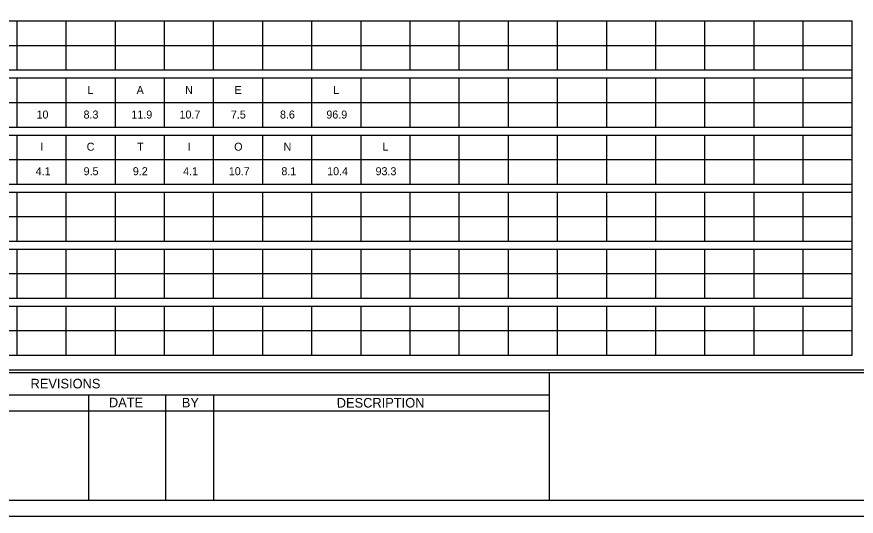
# Model space of a CAD drawing. Extents: x 17890628 to 17890844, y 17897506 to 17897992.
# Drawn here: x 17890726.43 to 17890772.14, y 17897507.81 to 17897535.03 of the extents above; entities that cross this region are included whole.
import ezdxf

# ---------------------------------------------------------------- set-up
doc = ezdxf.new("R2010")
doc.units = 0
for name, color, linetype in [('GSSign', 7, 'Continuous'), ('PlotBorder_dp', 7, 'Continuous'), ('SheetBorder_dp', 7, 'Continuous'), ('SheetLines_dp', 7, 'Continuous'), ('SheetLinesMisc2_dp', 7, 'Continuous'), ('TextMisc', 7, 'Continuous')]:
    doc.layers.add(name, color=color, linetype=linetype)

msp = doc.modelspace()

# ---------------------------------------------------------------- linework, layer by layer
at = {"layer": 'PlotBorder_dp'}
msp.add_lwpolyline([(17890700.471, 17897507.81), (17890844.155, 17897507.81), (17890844.155, 17897600.116), (17890700.471, 17897600.116)], close=True, dxfattribs=at)
at = {"layer": 'SheetBorder_dp'}
for p, q in [((17890705.26, 17897515.647), (17890839.365, 17897515.647)), ((17890705.26, 17897508.681), (17890839.365, 17897508.681))]:
    msp.add_line(p, q, dxfattribs=at)
at = {"layer": 'SheetLines_dp'}
for p, q in [((17890755.419, 17897515.647), (17890755.419, 17897508.681)), ((17890705.26, 17897514.428), (17890755.419, 17897514.428)), ((17890730.339, 17897514.428), (17890730.339, 17897508.681)), ((17890734.519, 17897514.428), (17890734.519, 17897508.681)), ((17890737.132, 17897514.428), (17890737.132, 17897508.681)), ((17890705.26, 17897513.557), (17890755.419, 17897513.557))]:
    msp.add_line(p, q, dxfattribs=at)
at = {"layer": 'SheetLinesMisc2_dp'}
for p, q in [((17890706.142, 17897534.804), (17890771.912, 17897534.804)), ((17890726.429, 17897534.804), (17890726.429, 17897532.131)), ((17890729.104, 17897534.804), (17890729.104, 17897532.131)), ((17890731.779, 17897534.804), (17890731.779, 17897532.131)), ((17890734.455, 17897534.804), (17890734.455, 17897532.131)), ((17890737.131, 17897534.804), (17890737.131, 17897532.131)), ((17890739.806, 17897534.804), (17890739.806, 17897532.131)), ((17890742.481, 17897534.804), (17890742.481, 17897532.131)), ((17890745.157, 17897534.804), (17890745.157, 17897532.131)), ((17890747.833, 17897534.804), (17890747.833, 17897532.131)), ((17890750.508, 17897534.804), (17890750.508, 17897532.131)), ((17890753.183, 17897534.804), (17890753.183, 17897532.131)), ((17890755.859, 17897534.804), (17890755.859, 17897532.131)), ((17890758.535, 17897534.804), (17890758.535, 17897532.131)), ((17890761.21, 17897534.804), (17890761.21, 17897532.131)), ((17890763.885, 17897534.804), (17890763.885, 17897532.131)), ((17890766.561, 17897534.804), (17890766.561, 17897532.131)), ((17890769.237, 17897534.804), (17890769.237, 17897532.131)), ((17890771.912, 17897516.593), (17890771.912, 17897534.804)), ((17890706.142, 17897533.468), (17890771.912, 17897533.468)), ((17890706.142, 17897532.131), (17890771.912, 17897532.131)), ((17890706.142, 17897531.696), (17890771.912, 17897531.696)), ((17890726.429, 17897531.696), (17890726.429, 17897529.023)), ((17890729.104, 17897531.696), (17890729.104, 17897529.023)), ((17890731.779, 17897531.696), (17890731.779, 17897529.023)), ((17890734.455, 17897531.696), (17890734.455, 17897529.023)), ((17890737.131, 17897531.696), (17890737.131, 17897529.023)), ((17890739.806, 17897531.696), (17890739.806, 17897529.023)), ((17890742.481, 17897531.696), (17890742.481, 17897529.023)), ((17890745.157, 17897531.696), (17890745.157, 17897529.023)), ((17890747.833, 17897531.696), (17890747.833, 17897529.023)), ((17890750.508, 17897531.696), (17890750.508, 17897529.023)), ((17890753.183, 17897531.696), (17890753.183, 17897529.023)), ((17890755.859, 17897531.696), (17890755.859, 17897529.023)), ((17890758.535, 17897531.696), (17890758.535, 17897529.023)), ((17890761.21, 17897531.696), (17890761.21, 17897529.023)), ((17890763.885, 17897531.696), (17890763.885, 17897529.023)), ((17890766.561, 17897531.696), (17890766.561, 17897529.023)), ((17890769.237, 17897531.696), (17890769.237, 17897529.023)), ((17890706.142, 17897530.359), (17890771.912, 17897530.359)), ((17890706.142, 17897529.023), (17890771.912, 17897529.023)), ((17890706.142, 17897528.588), (17890771.912, 17897528.588)), ((17890726.429, 17897528.588), (17890726.429, 17897525.916)), ((17890729.104, 17897528.588), (17890729.104, 17897525.916)), ((17890731.779, 17897528.588), (17890731.779, 17897525.916)), ((17890734.455, 17897528.588), (17890734.455, 17897525.916)), ((17890737.131, 17897528.588), (17890737.131, 17897525.916)), ((17890739.806, 17897528.588), (17890739.806, 17897525.916)), ((17890742.481, 17897528.588), (17890742.481, 17897525.916)), ((17890745.157, 17897528.588), (17890745.157, 17897525.916)), ((17890747.833, 17897528.588), (17890747.833, 17897525.916)), ((17890750.508, 17897528.588), (17890750.508, 17897525.916)), ((17890753.183, 17897528.588), (17890753.183, 17897525.916)), ((17890755.859, 17897528.588), (17890755.859, 17897525.916)), ((17890758.535, 17897528.588), (17890758.535, 17897525.916)), ((17890761.21, 17897528.588), (17890761.21, 17897525.916)), ((17890763.885, 17897528.588), (17890763.885, 17897525.916)), ((17890766.561, 17897528.588), (17890766.561, 17897525.916)), ((17890769.237, 17897528.588), (17890769.237, 17897525.916)), ((17890706.142, 17897527.252), (17890771.912, 17897527.252)), ((17890706.142, 17897525.916), (17890771.912, 17897525.916)), ((17890706.142, 17897525.48), (17890771.912, 17897525.48)), ((17890726.429, 17897525.48), (17890726.429, 17897522.808)), ((17890729.104, 17897525.48), (17890729.104, 17897522.808)), ((17890731.779, 17897525.48), (17890731.779, 17897522.808)), ((17890734.455, 17897525.48), (17890734.455, 17897522.808)), ((17890737.131, 17897525.48), (17890737.131, 17897522.808)), ((17890739.806, 17897525.48), (17890739.806, 17897522.808)), ((17890742.481, 17897525.48), (17890742.481, 17897522.808)), ((17890745.157, 17897525.48), (17890745.157, 17897522.808)), ((17890747.833, 17897525.48), (17890747.833, 17897522.808)), ((17890750.508, 17897525.48), (17890750.508, 17897522.808)), ((17890753.183, 17897525.48), (17890753.183, 17897522.808)), ((17890755.859, 17897525.48), (17890755.859, 17897522.808)), ((17890758.535, 17897525.48), (17890758.535, 17897522.808)), ((17890761.21, 17897525.48), (17890761.21, 17897522.808)), ((17890763.885, 17897525.48), (17890763.885, 17897522.808)), ((17890766.561, 17897525.48), (17890766.561, 17897522.808)), ((17890769.237, 17897525.48), (17890769.237, 17897522.808)), ((17890706.142, 17897524.145), (17890771.912, 17897524.145)), ((17890706.142, 17897522.808), (17890771.912, 17897522.808)), ((17890706.142, 17897522.372), (17890771.912, 17897522.372)), ((17890726.429, 17897522.372), (17890726.429, 17897519.7)), ((17890729.104, 17897522.372), (17890729.104, 17897519.7)), ((17890731.779, 17897522.372), (17890731.779, 17897519.7)), ((17890734.455, 17897522.372), (17890734.455, 17897519.7)), ((17890737.131, 17897522.372), (17890737.131, 17897519.7)), ((17890739.806, 17897522.372), (17890739.806, 17897519.7)), ((17890742.481, 17897522.372), (17890742.481, 17897519.7)), ((17890745.157, 17897522.372), (17890745.157, 17897519.7)), ((17890747.833, 17897522.372), (17890747.833, 17897519.7)), ((17890750.508, 17897522.372), (17890750.508, 17897519.7)), ((17890753.183, 17897522.372), (17890753.183, 17897519.7)), ((17890755.859, 17897522.372), (17890755.859, 17897519.7)), ((17890758.535, 17897522.372), (17890758.535, 17897519.7)), ((17890761.21, 17897522.372), (17890761.21, 17897519.7)), ((17890763.885, 17897522.372), (17890763.885, 17897519.7)), ((17890766.561, 17897522.372), (17890766.561, 17897519.7)), ((17890769.237, 17897522.372), (17890769.237, 17897519.7)), ((17890706.142, 17897521.036), (17890771.912, 17897521.036)), ((17890706.142, 17897519.7), (17890771.912, 17897519.7)), ((17890706.142, 17897519.264), (17890771.912, 17897519.264)), ((17890726.429, 17897519.264), (17890726.429, 17897516.593)), ((17890729.104, 17897519.264), (17890729.104, 17897516.593)), ((17890731.779, 17897519.264), (17890731.779, 17897516.593)), ((17890734.455, 17897519.264), (17890734.455, 17897516.593)), ((17890737.131, 17897519.264), (17890737.131, 17897516.593)), ((17890739.806, 17897519.264), (17890739.806, 17897516.593)), ((17890742.481, 17897519.264), (17890742.481, 17897516.593)), ((17890745.157, 17897519.264), (17890745.157, 17897516.593)), ((17890747.833, 17897519.264), (17890747.833, 17897516.593)), ((17890750.508, 17897519.264), (17890750.508, 17897516.593)), ((17890753.183, 17897519.264), (17890753.183, 17897516.593)), ((17890755.859, 17897519.264), (17890755.859, 17897516.593)), ((17890758.535, 17897519.264), (17890758.535, 17897516.593)), ((17890761.21, 17897519.264), (17890761.21, 17897516.593)), ((17890763.885, 17897519.264), (17890763.885, 17897516.593)), ((17890766.561, 17897519.264), (17890766.561, 17897516.593)), ((17890769.237, 17897519.264), (17890769.237, 17897516.593)), ((17890706.142, 17897517.928), (17890771.912, 17897517.928)), ((17890706.142, 17897516.593), (17890771.912, 17897516.593)), ((17890705.5, 17897515.791), (17890839.233, 17897515.791))]:
    msp.add_line(p, q, dxfattribs=at)

# ---------------------------------------------------------------- texts
at = {"layer": 'GSSign'}
for s, height, p in [('L', 0.436, (17890730.275, 17897530.822)), ('A', 0.436, (17890732.954, 17897530.822)), ('N', 0.436, (17890735.594, 17897530.822)), ('E', 0.436, (17890738.287, 17897530.822)), ('L', 0.436, (17890743.661, 17897530.822)), ('10', 0.4357, (17890727.504, 17897529.485)), ('8.3', 0.4357, (17890730.064, 17897529.485)), ('11.9', 0.4357, (17890732.67, 17897529.485)), ('10.7', 0.4357, (17890735.29, 17897529.485)), ('7.5', 0.4357, (17890738.088, 17897529.485)), ('8.6', 0.4357, (17890740.761, 17897529.485)), ('96.9', 0.4357, (17890743.287, 17897529.485)), ('I', 0.436, (17890727.715, 17897527.732)), ('C', 0.436, (17890730.234, 17897527.732)), ('T', 0.436, (17890732.981, 17897527.732)), ('I', 0.436, (17890735.741, 17897527.732)), ('O', 0.436, (17890738.268, 17897527.732)), ('N', 0.436, (17890740.958, 17897527.732)), ('L', 0.436, (17890746.34, 17897527.732)), ('4.1', 0.4357, (17890727.462, 17897526.396)), ('9.5', 0.4357, (17890730.066, 17897526.396)), ('9.2', 0.4357, (17890732.749, 17897526.396)), ('4.1', 0.4357, (17890735.488, 17897526.396)), ('10.7', 0.4357, (17890737.975, 17897526.396)), ('8.1', 0.4357, (17890740.838, 17897526.396)), ('10.4', 0.4357, (17890743.33, 17897526.396)), ('93.3', 0.4357, (17890745.967, 17897526.396))]:
    msp.add_text(s, height=height, dxfattribs=at).set_placement(p)
at = {"layer": 'TextMisc'}
for s, p in [('REVISIONS', (17890727.178, 17897514.776)), ('BY', (17890735.416, 17897513.74))]:
    msp.add_text(s, height=0.5225, dxfattribs=at).set_placement(p)
for s, height, rotation, p in [('DATE', 0.5225, 359.8693, (17890731.445, 17897513.749)), ('DESCRIPTION', 0.52238, 0.0498, (17890743.854, 17897513.731))]:
    msp.add_text(s, height=height, rotation=rotation, dxfattribs=at).set_placement(p)

doc.saveas('drawing.dxf')
